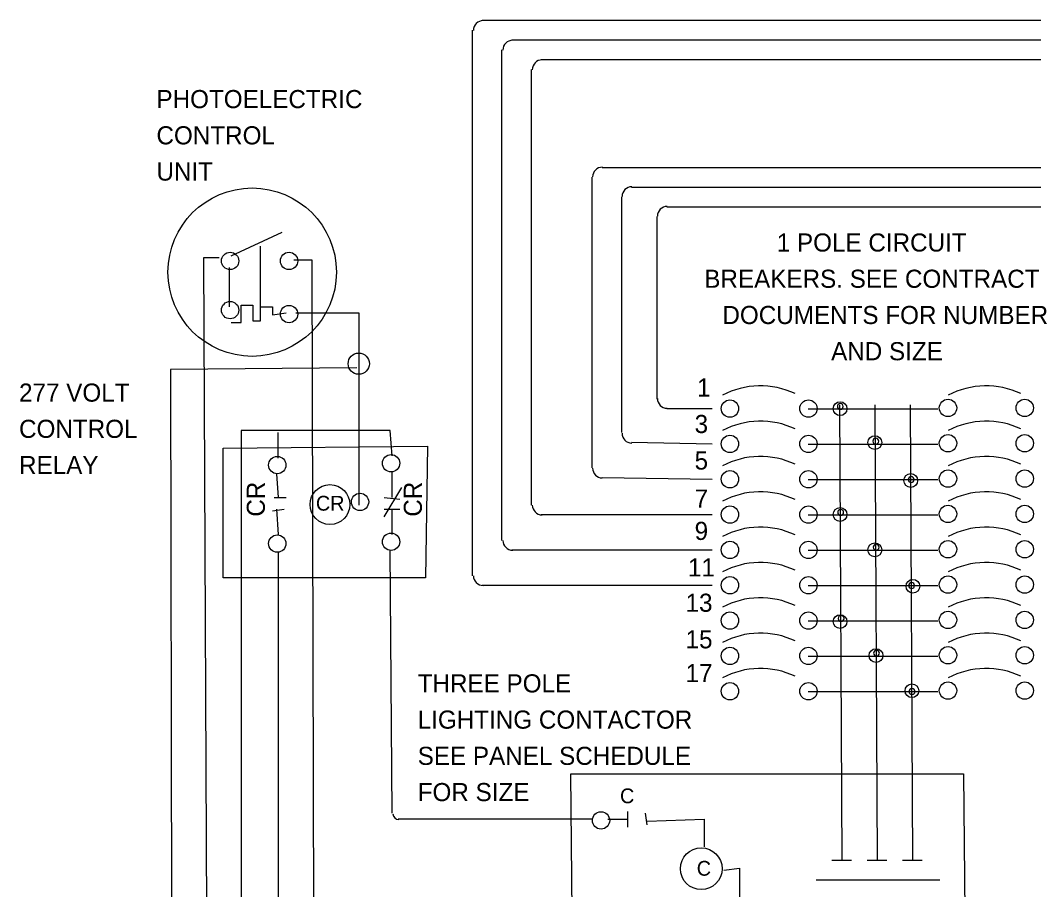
# Model space of a CAD drawing. Extents: x 10006.6 to 10036.5, y 10000 to 10010.3.
# Drawn here: x 10029.75 to 10033.106, y 10007.122 to 10010.001 of the extents above; entities that cross this region are included whole.
import ezdxf

# ---------------------------------------------------------------- set-up
doc = ezdxf.new("R2010")
doc.units = 0
doc.layers.add('DETL-LINE', color=7, linetype='Continuous')
doc.layers.add('DETL-NOTE', color=7, linetype='Continuous')

# ---------------------------------------------------------------- blocks, each defined once
blk = doc.blocks.new('CIR1')
at = {"layer": 'DETL-LINE'}
blk.add_circle((0, 0), 0.0589, dxfattribs=at)

msp = doc.modelspace()

# ---------------------------------------------------------------- linework, layer by layer
at = {"layer": 'DETL-LINE'}
for p, q in [((10031.28, 10010.001), (10034.89, 10010.001)), ((10031.248, 10008.161), (10031.248, 10009.968)), ((10031.378, 10009.936), (10034.89, 10009.936)), ((10031.345, 10008.278), (10031.345, 10009.903)), ((10031.475, 10009.871), (10034.89, 10009.871)), ((10031.443, 10008.395), (10031.443, 10009.838)), ((10031.677, 10009.513), (10034.89, 10009.513)), ((10031.644, 10008.519), (10031.644, 10009.481)), ((10031.774, 10009.448), (10034.89, 10009.448)), ((10031.742, 10008.636), (10031.742, 10009.416)), ((10031.891, 10009.383), (10034.89, 10009.383)), ((10031.859, 10008.746), (10031.859, 10009.351)), ((10030.448, 10009.221), (10030.617, 10009.299)), ((10030.546, 10009.052), (10030.546, 10009.253)), ((10030.357, 10009.214), (10030.37, 10006.172)), ((10030.409, 10009.214), (10030.357, 10009.214)), ((10030.656, 10009.208), (10030.715, 10009.208)), ((10030.715, 10009.208), (10030.721, 10006.861)), ((10030.442, 10009.182), (10030.442, 10009.052)), ((10030.481, 10009.058), (10030.52, 10009.058)), ((10030.481, 10009), (10030.481, 10009.058)), ((10030.52, 10009.058), (10030.52, 10009.006)), ((10030.546, 10009.052), (10030.585, 10009.052)), ((10030.546, 10009.006), (10030.546, 10009.052)), ((10030.585, 10009.052), (10030.585, 10009.026)), ((10030.52, 10009.006), (10030.546, 10009.006)), ((10030.585, 10009.026), (10030.63, 10009.032)), ((10030.663, 10009.032), (10030.871, 10009.032)), ((10030.871, 10009.032), (10030.871, 10008.395)), ((10030.448, 10009), (10030.481, 10009)), ((10030.864, 10008.85), (10030.247, 10008.844)), ((10030.247, 10008.844), (10030.253, 10005.951)), ((10032.041, 10008.714), (10031.891, 10008.714)), ((10032.359, 10008.714), (10032.788, 10008.714)), ((10032.463, 10008.727), (10032.47, 10007.219)), ((10032.58, 10008.727), (10032.587, 10007.219)), ((10032.697, 10008.727), (10032.704, 10007.219)), ((10030.481, 10008.642), (10030.481, 10006.075)), ((10030.611, 10008.642), (10030.481, 10008.642)), ((10030.604, 10008.551), (10030.604, 10008.636)), ((10030.975, 10008.642), (10030.611, 10008.642)), ((10030.981, 10008.558), (10030.975, 10008.642)), ((10032.041, 10008.597), (10031.774, 10008.603)), ((10030.422, 10008.584), (10031.098, 10008.59)), ((10030.422, 10008.155), (10030.422, 10008.584)), ((10031.098, 10008.59), (10031.092, 10008.155)), ((10032.359, 10008.597), (10032.788, 10008.597)), ((10030.598, 10008.499), (10030.604, 10008.421)), ((10030.981, 10008.421), (10030.981, 10008.506)), ((10032.041, 10008.48), (10031.677, 10008.486)), ((10032.359, 10008.48), (10032.788, 10008.48)), ((10030.955, 10008.356), (10031.014, 10008.454)), ((10030.591, 10008.421), (10030.63, 10008.421)), ((10030.955, 10008.421), (10031.007, 10008.415)), ((10030.585, 10008.376), (10030.624, 10008.382)), ((10030.598, 10008.382), (10030.604, 10008.298)), ((10030.955, 10008.382), (10031.007, 10008.382)), ((10030.981, 10008.298), (10030.981, 10008.382)), ((10032.041, 10008.363), (10031.475, 10008.363)), ((10032.359, 10008.363), (10032.788, 10008.363)), ((10030.604, 10008.239), (10030.604, 10007.069)), ((10030.981, 10007.375), (10030.975, 10008.246)), ((10032.041, 10008.246), (10031.378, 10008.246)), ((10032.359, 10008.246), (10032.788, 10008.246)), ((10031.092, 10008.155), (10030.422, 10008.155)), ((10032.041, 10008.129), (10031.28, 10008.129)), ((10032.359, 10008.129), (10032.788, 10008.129)), ((10032.359, 10008.012), (10032.788, 10008.012)), ((10032.359, 10007.895), (10032.788, 10007.895)), ((10032.359, 10007.778), (10032.788, 10007.778)), ((10031.579, 10006.861), (10031.573, 10007.505)), ((10031.573, 10007.505), (10032.873, 10007.505)), ((10032.873, 10007.505), (10032.879, 10006.868)), ((10031.761, 10007.381), (10031.761, 10007.329)), ((10031.826, 10007.336), (10031.82, 10007.375)), ((10031.644, 10007.355), (10031.001, 10007.355)), ((10031.696, 10007.355), (10031.761, 10007.355)), ((10031.826, 10007.349), (10032.015, 10007.355)), ((10032.015, 10007.355), (10032.015, 10007.264)), ((10032.08, 10007.186), (10032.132, 10007.193)), ((10032.132, 10007.193), (10032.132, 10007.056)), ((10032.437, 10007.219), (10032.502, 10007.219)), ((10032.554, 10007.219), (10032.619, 10007.219)), ((10032.671, 10007.219), (10032.736, 10007.219)), ((10032.385, 10007.154), (10032.795, 10007.154))]:
    msp.add_line(p, q, dxfattribs=at)
for centre, radius in [((10030.518, 10009.1668), 0.2788), ((10030.8708, 10008.8636), 0.0351), ((10032.4646, 10008.7147), 0.0228), ((10032.5797, 10008.6022), 0.0228), ((10032.6986, 10008.4768), 0.0228), ((10030.7756, 10008.3972), 0.0659), ((10032.4646, 10008.3643), 0.0228), ((10032.5797, 10008.2473), 0.0228), ((10032.7058, 10008.1264), 0.0228), ((10032.4646, 10008.0094), 0.0228), ((10032.5836, 10007.897), 0.0228), ((10032.7025, 10007.7806), 0.0228), ((10032.0049, 10007.1912), 0.0691)]:
    msp.add_circle(centre, radius, dxfattribs=at)
for centre, radius, start, end in [((10031.2831, 10009.9673), 0.0325, 90, 180), ((10031.3806, 10009.9023), 0.0325, 90, 180), ((10031.4781, 10009.8373), 0.0325, 90, 180), ((10031.6777, 10009.4821), 0.0325, 90, 180), ((10031.7752, 10009.4171), 0.0325, 90, 180), ((10031.8922, 10009.3521), 0.0325, 90, 180), ((10032.2008, 10008.5232), 0.2673, 64.5012, 118.0668), ((10032.9483, 10008.5232), 0.2673, 64.5012, 118.0668), ((10031.8922, 10008.7485), 0.0325, 180, 269.2464), ((10032.4653, 10008.7221), 0.00975, 0, 180), ((10032.4653, 10008.7221), 0.00975, 180, 0), ((10032.2008, 10008.4062), 0.2673, 64.5012, 118.0668), ((10032.9483, 10008.4062), 0.2673, 64.5012, 118.0668), ((10031.7752, 10008.6332), 0.0325, 180, 269.2113), ((10032.5827, 10008.6069), 0.00975, 0, 180), ((10032.5827, 10008.6069), 0.00975, 180, 0), ((10032.2008, 10008.2892), 0.2673, 64.5012, 118.0668), ((10032.9483, 10008.2892), 0.2673, 64.5012, 118.0668), ((10031.6777, 10008.5178), 0.0325, 180, 269.1559), ((10032.7002, 10008.4798), 0.00975, 0, 180), ((10032.7002, 10008.4798), 0.00975, 180, 0), ((10032.2008, 10008.1722), 0.2673, 64.5012, 118.0668), ((10032.9483, 10008.1722), 0.2673, 64.5012, 118.0668), ((10031.4781, 10008.3955), 0.0325, 180, 270), ((10032.4666, 10008.3711), 0.00975, 0, 180), ((10032.4666, 10008.3711), 0.00975, 180, 0), ((10032.2008, 10008.0552), 0.2673, 64.5012, 118.0668), ((10032.9483, 10008.0552), 0.2673, 64.5012, 118.0668), ((10031.3806, 10008.2785), 0.0325, 180, 270), ((10032.584, 10008.2559), 0.00975, 0, 180), ((10032.584, 10008.2559), 0.00975, 180, 0), ((10032.2008, 10007.9382), 0.2673, 64.5012, 118.0668), ((10032.9483, 10007.9382), 0.2673, 64.5012, 118.0668), ((10031.2831, 10008.1615), 0.0325, 180, 270), ((10032.7015, 10008.1288), 0.00975, 0, 180), ((10032.7015, 10008.1288), 0.00975, 180, 0), ((10032.2008, 10007.8212), 0.2673, 64.5012, 118.0668), ((10032.9483, 10007.8212), 0.2673, 64.5012, 118.0668), ((10032.4679, 10008.0201), 0.00975, 0, 180), ((10032.4679, 10008.0201), 0.00975, 180, 0), ((10032.2008, 10007.7042), 0.2673, 64.5012, 118.0668), ((10032.9483, 10007.7042), 0.2673, 64.5012, 118.0668), ((10032.5853, 10007.905), 0.00975, 0, 180), ((10032.5853, 10007.905), 0.00975, 180, 0), ((10032.2008, 10007.5872), 0.2673, 64.5012, 118.0668), ((10032.9483, 10007.5872), 0.2673, 64.5012, 118.0668), ((10032.7028, 10007.7778), 0.00975, 0, 180), ((10032.7028, 10007.7778), 0.00975, 180, 0), ((10031.0035, 10007.3734), 0.0195, 180.3454, 270.3243)]:
    msp.add_arc(centre, radius, start, end, dxfattribs=at)

# ---------------------------------------------------------------- block references
at = {"layer": 'DETL-LINE', "xscale": 0.4875000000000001, "yscale": 0.4875000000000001}
for p in [(10030.445, 10009.204), (10030.64, 10009.204), (10030.445, 10009.041), (10030.64, 10009.028), (10032.1, 10008.715), (10032.36, 10008.715), (10032.822, 10008.717), (10033.076, 10008.717), (10032.1, 10008.598), (10032.36, 10008.598), (10032.822, 10008.6), (10033.076, 10008.6), (10030.601, 10008.528), (10030.978, 10008.534), (10032.1, 10008.481), (10032.36, 10008.481), (10032.822, 10008.483), (10033.076, 10008.483), (10030.875, 10008.406), (10032.1, 10008.364), (10032.36, 10008.364), (10032.822, 10008.366), (10033.076, 10008.366), (10030.601, 10008.268), (10030.978, 10008.274), (10032.1, 10008.247), (10032.36, 10008.247), (10032.822, 10008.249), (10033.076, 10008.249), (10032.1, 10008.13), (10032.36, 10008.13), (10032.822, 10008.132), (10033.076, 10008.132), (10032.1, 10008.013), (10032.36, 10008.013), (10032.822, 10008.015), (10033.076, 10008.015), (10032.1, 10007.896), (10032.36, 10007.896), (10032.822, 10007.898), (10033.076, 10007.898), (10032.1, 10007.779), (10032.36, 10007.779), (10032.822, 10007.781), (10033.076, 10007.781), (10031.673, 10007.351)]:
    msp.add_blockref('CIR1', p, dxfattribs=at)

# ---------------------------------------------------------------- texts
at = {"layer": 'DETL-NOTE'}
for s, height, p in [('PHOTOELECTRIC', 0.06, (10030.201, 10009.71)), ('CONTROL', 0.06, (10030.201, 10009.59)), ('UNIT', 0.06, (10030.201, 10009.47)), ('1 POLE CIRCUIT', 0.06, (10032.255, 10009.235)), ('BREAKERS. SEE CONTRACT', 0.06, (10032.015, 10009.115)), ('DOCUMENTS FOR NUMBER', 0.06, (10032.075, 10008.995)), ('AND SIZE', 0.06, (10032.435, 10008.875)), ('1', 0.06, (10031.991, 10008.755)), ('277 VOLT', 0.06, (10029.746, 10008.738)), ('CONTROL', 0.06, (10029.746, 10008.618)), ('3', 0.06, (10031.983, 10008.634)), ('5', 0.06, (10031.983, 10008.513)), ('RELAY', 0.06, (10029.746, 10008.498)), ('7', 0.06, (10031.983, 10008.387)), ('CR', 0.049, (10030.729, 10008.377)), ('9', 0.06, (10031.983, 10008.28)), ('11', 0.06, (10031.961, 10008.159)), ('13', 0.06, (10031.953, 10008.042)), ('15', 0.06, (10031.953, 10007.921)), ('17', 0.06, (10031.953, 10007.809)), ('THREE POLE', 0.06, (10031.066, 10007.775)), ('LIGHTING CONTACTOR', 0.06, (10031.066, 10007.655)), ('SEE PANEL SCHEDULE', 0.06, (10031.066, 10007.535)), ('FOR SIZE', 0.06, (10031.066, 10007.415)), ('C', 0.049, (10031.736, 10007.408)), ('C', 0.049, (10031.99, 10007.168))]:
    msp.add_text(s, height=height, dxfattribs=at).set_placement(p)
for p in [(10030.56, 10008.357), (10031.08, 10008.357)]:
    msp.add_text('CR', height=0.06, rotation=90, dxfattribs=at).set_placement(p)

doc.saveas('drawing.dxf')
